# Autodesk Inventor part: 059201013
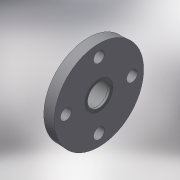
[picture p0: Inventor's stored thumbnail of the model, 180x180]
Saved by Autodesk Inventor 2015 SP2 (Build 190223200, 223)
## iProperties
Created: 2017-10
Part Number: 059201013
Material: Generic
Description: PLASSON THR. FIXED FLANGE PVC 1.1/4"
Document SubType Name: Modeling
Designer: KIM
Density: 1 g/cm^3
Appearance: Default
Author: KIM
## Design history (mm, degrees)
derived "059201.ipt"
feature "Solid1::059201.ipt"
tag "TaggingFeature1"
body "Solid1"
other parameters: "d0" = 27, "d3" = 138.6, "d14" = 18, "d16" = 27, "d17" = 0, "d19" = 360 deg, "d21" = 22, "d22" = 38.952, "d23" = 37.0044, "d25" = 0.38952, "d26" = 0.7, "d27" = 0.7, "d28" = 0.7, "d29" = 0.7, "d30" = 0.7, "d31" = 0.7, "d32" = 0.28, "d33" = 0, "d34" = 15, "d35" = 46.7424, "H_" = 27, "S_" = 18, "lt_" = 22, "G_" = 38.952, "H_1" = 15
